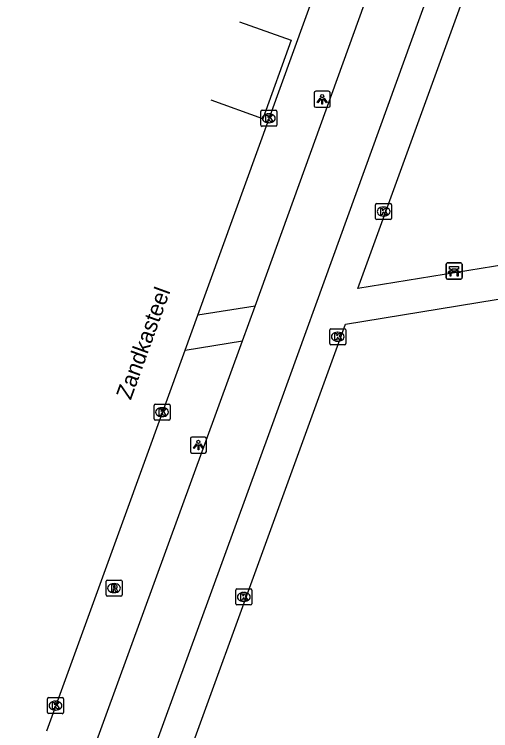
# Model space of a CAD drawing. Extents: x 156664 to 157568, y 383571 to 384421.
# Drawn here: x 156762.62 to 156792.33, y 384130.69 to 384175.37 of the extents above; entities that cross this region are included whole.
import ezdxf

# ---------------------------------------------------------------- set-up
doc = ezdxf.new("R2010")
doc.units = 0
for name, color, linetype in [('IMGEO_Bank', 7, 'Continuous'), ('IMGEO_Fietspad_open', 7, 'Continuous'), ('IMGEO_Kolk', 7, 'Continuous'), ('IMGEO_Lichtpunt', 7, 'Continuous'), ('IMGEO_Openbare_ruimte_label', 7, 'Continuous'), ('IMGEO_Rijbaan_lokaal_open', 7, 'Continuous'), ('IMGEO_Rioolput', 7, 'Continuous'), ('IMGEO_Voetpad_open', 7, 'Continuous')]:
    doc.layers.add(name, color=color, linetype=linetype)

msp = doc.modelspace()

# ---------------------------------------------------------------- linework, layer by layer
at = {"layer": 'IMGEO_Bank'}
for p, q in [((156789.62, 384159.863), (156790.461, 384159.863)), ((156790.461, 384159.863), (156789.62, 384159.863)), ((156789.545, 384158.938), (156789.545, 384159.779)), ((156789.545, 384159.779), (156789.545, 384158.938)), ((156789.854, 384159.369), (156789.854, 384159.475)), ((156789.898, 384159.475), (156789.898, 384159.369)), ((156790.186, 384159.481), (156789.904, 384159.481)), ((156790.192, 384159.369), (156790.192, 384159.475)), ((156790.236, 384159.475), (156790.236, 384159.369)), ((156790.545, 384159.788), (156790.545, 384158.947)), ((156790.545, 384158.947), (156790.545, 384159.788)), ((156790.242, 384159.261), (156789.849, 384159.261)), ((156789.904, 384159.363), (156790.186, 384159.363)), ((156790.47, 384158.863), (156789.629, 384158.863)), ((156789.629, 384158.863), (156790.47, 384158.863))]:
    msp.add_line(p, q, dxfattribs=at)
for points in [[(156789.848, 384159.481), (156789.762, 384159.481), (156789.762, 384159.642), (156790.325, 384159.642), (156790.325, 384159.481), (156790.242, 384159.481)], [(156789.792, 384159.261), (156789.65, 384159.261), (156789.762, 384159.363), (156789.848, 384159.363)], [(156789.842, 384159.254), (156789.842, 384159.047), (156789.799, 384159.047), (156789.799, 384159.254)], [(156790.242, 384159.363), (156790.325, 384159.363), (156790.437, 384159.261), (156790.298, 384159.261)], [(156790.292, 384159.254), (156790.292, 384159.047), (156790.248, 384159.047), (156790.248, 384159.254)]]:
    msp.add_lwpolyline(points, dxfattribs=at)
for centre, radius, start, end in [((156789.623, 384159.785), 0.0779, 92.4484, 184.2845), ((156789.623, 384159.785), 0.0779, 92.4484, 184.2845), ((156790.467, 384159.785), 0.0779, 2.4484, 94.2845), ((156790.467, 384159.785), 0.0779, 2.4484, 94.2845), ((156789.847, 384159.474), 0.00671, 2.8957, 87.1043), ((156789.904, 384159.474), 0.00671, 92.8957, 177.1043), ((156790.186, 384159.474), 0.00671, 2.8957, 87.1043), ((156790.243, 384159.474), 0.00671, 92.8957, 177.1043), ((156789.792, 384159.254), 0.00671, 2.8957, 87.1043), ((156789.849, 384159.254), 0.00671, 92.8957, 177.1043), ((156789.847, 384159.37), 0.00671, 272.8957, 357.1043), ((156789.904, 384159.37), 0.00671, 182.8957, 267.1043), ((156790.186, 384159.37), 0.00671, 272.8957, 357.1043), ((156790.243, 384159.37), 0.00671, 182.8957, 267.1043), ((156790.241, 384159.254), 0.00671, 2.8957, 87.1043), ((156790.298, 384159.254), 0.00671, 92.8957, 177.1043), ((156789.623, 384158.941), 0.0779, 182.4484, 274.2845), ((156789.623, 384158.941), 0.0779, 182.4484, 274.2845), ((156790.467, 384158.941), 0.0779, 272.4484, 4.2845), ((156790.467, 384158.941), 0.0779, 272.4484, 4.2845)]:
    msp.add_arc(centre, radius, start, end, dxfattribs=at)
at = {"layer": 'IMGEO_Fietspad_open'}
for points in [[(156833.031, 384293.583), (156831.476, 384295.664), (156797.885, 384202.753), (156781.915, 384158.669), (156778.633, 384149.604), (156765.945, 384114.759), (156745.635, 384058.756), (156737.507, 384036.302), (156716.373, 383978.18), (156709.217, 383958.49), (156701.659, 383937.694), (156690.408, 383906.735), (156677.045, 383870.138), (156675.34, 383865.46)], [(156777.633, 384157.17), (156795.089, 384205.43)], [(156776.852, 384155.017), (156777.633, 384157.17)], [(156765.926, 384125.001), (156776.852, 384155.017)]]:
    msp.add_lwpolyline(points, dxfattribs=at)
at = {"layer": 'IMGEO_Kolk'}
for p, q in [((156777.994, 384168.46), (156777.994, 384169.312)), ((156778.069, 384169.386), (156778.921, 384169.386)), ((156778.995, 384169.312), (156778.995, 384168.46)), ((156778.482, 384169.166), (156778.507, 384169.166)), ((156778.921, 384168.386), (156778.069, 384168.386)), ((156778.505, 384168.606), (156778.48, 384168.606)), ((156785.148, 384162.645), (156785.148, 384163.497)), ((156785.223, 384163.571), (156786.075, 384163.571)), ((156786.149, 384163.497), (156786.149, 384162.645)), ((156785.636, 384163.351), (156785.661, 384163.351)), ((156786.075, 384162.571), (156785.223, 384162.571)), ((156785.659, 384162.791), (156785.634, 384162.791)), ((156782.292, 384154.837), (156782.292, 384155.689)), ((156782.367, 384155.763), (156783.219, 384155.763)), ((156782.78, 384155.543), (156782.805, 384155.543)), ((156783.293, 384155.689), (156783.293, 384154.837)), ((156782.803, 384154.983), (156782.778, 384154.983)), ((156783.219, 384154.763), (156782.367, 384154.763)), ((156771.336, 384150.132), (156771.336, 384150.984)), ((156771.411, 384151.058), (156772.263, 384151.058)), ((156772.337, 384150.984), (156772.337, 384150.132)), ((156771.824, 384150.838), (156771.849, 384150.838)), ((156772.263, 384150.058), (156771.411, 384150.058)), ((156771.847, 384150.278), (156771.822, 384150.278)), ((156776.432, 384138.608), (156776.432, 384139.46)), ((156776.507, 384139.534), (156777.359, 384139.534)), ((156776.92, 384139.314), (156776.945, 384139.314)), ((156777.433, 384139.46), (156777.433, 384138.608)), ((156777.359, 384138.534), (156776.507, 384138.534)), ((156776.943, 384138.754), (156776.918, 384138.754)), ((156764.689, 384131.828), (156764.689, 384132.68)), ((156764.764, 384132.754), (156765.616, 384132.754)), ((156765.69, 384132.68), (156765.69, 384131.828)), ((156765.177, 384132.534), (156765.202, 384132.534)), ((156765.616, 384131.754), (156764.764, 384131.754)), ((156765.2, 384131.974), (156765.175, 384131.974))]:
    msp.add_line(p, q, dxfattribs=at)
for points in [[(156777.994, 384168.46), (156777.994, 384169.312)], [(156778.069, 384169.386), (156778.921, 384169.386)], [(156778.995, 384169.312), (156778.995, 384168.46)], [(156778.315, 384169.086), (156778.438, 384169.086), (156778.438, 384168.935), (156778.568, 384169.086), (156778.732, 384169.086), (156778.586, 384168.935), (156778.739, 384168.686), (156778.587, 384168.686), (156778.502, 384168.85), (156778.438, 384168.783), (156778.438, 384168.686), (156778.315, 384168.686), (156778.315, 384169.086)], [(156778.921, 384168.386), (156778.069, 384168.386)], [(156785.148, 384162.645), (156785.148, 384163.497)], [(156785.223, 384163.571), (156786.075, 384163.571)], [(156786.149, 384163.497), (156786.149, 384162.645)], [(156785.469, 384163.271), (156785.592, 384163.271), (156785.592, 384163.12), (156785.722, 384163.271), (156785.886, 384163.271), (156785.74, 384163.12), (156785.893, 384162.871), (156785.741, 384162.871), (156785.656, 384163.035), (156785.592, 384162.968), (156785.592, 384162.871), (156785.469, 384162.871), (156785.469, 384163.271)], [(156786.075, 384162.571), (156785.223, 384162.571)], [(156782.292, 384154.837), (156782.292, 384155.689)], [(156782.367, 384155.763), (156783.219, 384155.763)], [(156782.613, 384155.463), (156782.736, 384155.463), (156782.736, 384155.312), (156782.866, 384155.463), (156783.03, 384155.463), (156782.884, 384155.312), (156783.037, 384155.063), (156782.885, 384155.063), (156782.8, 384155.227), (156782.736, 384155.16), (156782.736, 384155.063), (156782.613, 384155.063), (156782.613, 384155.463)], [(156783.293, 384155.689), (156783.293, 384154.837)], [(156783.219, 384154.763), (156782.367, 384154.763)], [(156771.336, 384150.132), (156771.336, 384150.984)], [(156771.411, 384151.058), (156772.263, 384151.058)], [(156772.337, 384150.984), (156772.337, 384150.132)], [(156771.657, 384150.758), (156771.78, 384150.758), (156771.78, 384150.607), (156771.91, 384150.758), (156772.074, 384150.758), (156771.928, 384150.607), (156772.081, 384150.358), (156771.929, 384150.358), (156771.844, 384150.522), (156771.78, 384150.455), (156771.78, 384150.358), (156771.657, 384150.358), (156771.657, 384150.758)], [(156772.263, 384150.058), (156771.411, 384150.058)], [(156776.432, 384138.608), (156776.432, 384139.46)], [(156776.507, 384139.534), (156777.359, 384139.534)], [(156777.433, 384139.46), (156777.433, 384138.608)], [(156776.753, 384139.234), (156776.876, 384139.234), (156776.876, 384139.083), (156777.006, 384139.234), (156777.17, 384139.234), (156777.024, 384139.083), (156777.177, 384138.834), (156777.025, 384138.834), (156776.94, 384138.998), (156776.876, 384138.931), (156776.876, 384138.834), (156776.753, 384138.834), (156776.753, 384139.234)], [(156777.359, 384138.534), (156776.507, 384138.534)], [(156764.689, 384131.828), (156764.689, 384132.68)], [(156764.764, 384132.754), (156765.616, 384132.754)], [(156765.69, 384132.68), (156765.69, 384131.828)], [(156765.01, 384132.454), (156765.133, 384132.454), (156765.133, 384132.303), (156765.263, 384132.454), (156765.427, 384132.454), (156765.281, 384132.303), (156765.434, 384132.054), (156765.282, 384132.054), (156765.197, 384132.218), (156765.133, 384132.151), (156765.133, 384132.054), (156765.01, 384132.054), (156765.01, 384132.454)], [(156765.616, 384131.754), (156764.764, 384131.754)]]:
    msp.add_lwpolyline(points, dxfattribs=at)
for centre, start, end in [((156778.071, 384169.31), 91.552, 178.448), ((156778.071, 384169.31), 91.552, 178.448), ((156778.919, 384169.31), 1.552, 88.448), ((156778.919, 384169.31), 1.552, 88.448), ((156778.071, 384168.462), 181.552, 268.448), ((156778.071, 384168.462), 181.552, 268.448), ((156778.919, 384168.462), 271.552, 358.448), ((156778.919, 384168.462), 271.552, 358.448), ((156785.225, 384163.495), 91.552, 178.448), ((156785.225, 384163.495), 91.552, 178.448), ((156786.073, 384163.495), 1.552, 88.448), ((156786.073, 384163.495), 1.552, 88.448), ((156785.225, 384162.647), 181.552, 268.448), ((156785.225, 384162.647), 181.552, 268.448), ((156786.073, 384162.647), 271.552, 358.448), ((156786.073, 384162.647), 271.552, 358.448), ((156782.369, 384155.687), 91.552, 178.448), ((156782.369, 384155.687), 91.552, 178.448), ((156783.217, 384155.687), 1.552, 88.448), ((156783.217, 384155.687), 1.552, 88.448), ((156782.369, 384154.839), 181.552, 268.448), ((156782.369, 384154.839), 181.552, 268.448), ((156783.217, 384154.839), 271.552, 358.448), ((156783.217, 384154.839), 271.552, 358.448), ((156771.413, 384150.982), 91.552, 178.448), ((156771.413, 384150.982), 91.552, 178.448), ((156772.261, 384150.982), 1.552, 88.448), ((156772.261, 384150.982), 1.552, 88.448), ((156771.413, 384150.134), 181.552, 268.448), ((156771.413, 384150.134), 181.552, 268.448), ((156772.261, 384150.134), 271.552, 358.448), ((156772.261, 384150.134), 271.552, 358.448), ((156776.509, 384139.458), 91.552, 178.448), ((156776.509, 384139.458), 91.552, 178.448), ((156777.357, 384139.458), 1.552, 88.448), ((156777.357, 384139.458), 1.552, 88.448), ((156776.509, 384138.61), 181.552, 268.448), ((156776.509, 384138.61), 181.552, 268.448), ((156777.357, 384138.61), 271.552, 358.448), ((156777.357, 384138.61), 271.552, 358.448), ((156764.766, 384132.678), 91.552, 178.448), ((156764.766, 384132.678), 91.552, 178.448), ((156765.614, 384132.678), 1.552, 88.448), ((156765.614, 384132.678), 1.552, 88.448), ((156764.766, 384131.83), 181.552, 268.448), ((156764.766, 384131.83), 181.552, 268.448), ((156765.614, 384131.83), 271.552, 358.448), ((156765.614, 384131.83), 271.552, 358.448)]:
    msp.add_arc(centre, 0.0765, start, end, dxfattribs=at)
for centre, major_axis, ratio, start_param, end_param in [((156778.481, 384168.886), (-0.387, 0.002), 0.722429, 4.712389, 7.853982), ((156778.506, 384168.886), (-0.39, 0.002), 0.717154, 1.570796, 4.712389), ((156785.635, 384163.071), (-0.387, 0.002), 0.722429, 4.712389, 7.853982), ((156785.66, 384163.071), (-0.39, 0.002), 0.717154, 1.570796, 4.712389), ((156782.779, 384155.263), (-0.387, 0.002), 0.722429, 4.712389, 7.853982), ((156782.804, 384155.263), (-0.39, 0.002), 0.717154, 1.570796, 4.712389), ((156771.823, 384150.558), (-0.387, 0.002), 0.722429, 4.712389, 7.853982), ((156771.848, 384150.558), (-0.39, 0.002), 0.717154, 1.570796, 4.712389), ((156776.919, 384139.034), (-0.387, 0.002), 0.722429, 4.712389, 7.853982), ((156776.944, 384139.034), (-0.39, 0.002), 0.717154, 1.570796, 4.712389), ((156765.176, 384132.254), (-0.387, 0.002), 0.722429, 4.712389, 7.853982), ((156765.201, 384132.254), (-0.39, 0.002), 0.717154, 1.570796, 4.712389)]:
    msp.add_ellipse(centre, major_axis=major_axis, ratio=ratio, start_param=start_param, end_param=end_param, dxfattribs=at)
at = {"layer": 'IMGEO_Lichtpunt'}
for p, q in [((156781.323, 384170.474), (156781.323, 384169.667)), ((156781.323, 384170.474), (156781.323, 384169.667)), ((156782.225, 384170.569), (156781.417, 384170.569)), ((156782.225, 384170.569), (156781.417, 384170.569)), ((156782.319, 384169.667), (156782.319, 384170.474)), ((156782.319, 384169.667), (156782.319, 384170.474)), ((156781.417, 384169.573), (156782.225, 384169.573)), ((156781.417, 384169.573), (156782.225, 384169.573)), ((156773.602, 384148.911), (156773.602, 384148.104)), ((156773.602, 384148.911), (156773.602, 384148.104)), ((156774.504, 384149.006), (156773.696, 384149.006)), ((156774.504, 384149.006), (156773.696, 384149.006)), ((156774.598, 384148.104), (156774.598, 384148.911)), ((156774.598, 384148.104), (156774.598, 384148.911)), ((156773.696, 384148.01), (156774.504, 384148.01)), ((156773.696, 384148.01), (156774.504, 384148.01))]:
    msp.add_line(p, q, dxfattribs=at)
for points in [[(156781.697, 384170.138), (156781.736, 384170.11), (156781.548, 384169.848), (156781.51, 384169.875), (156781.697, 384170.138)], [(156781.909, 384170.11), (156781.947, 384170.137), (156782.134, 384169.875), (156782.095, 384169.847), (156781.909, 384170.11)], [(156781.799, 384170.09), (156781.846, 384170.09), (156781.846, 384169.768), (156781.799, 384169.768), (156781.799, 384170.09)], [(156773.976, 384148.575), (156774.015, 384148.547), (156773.827, 384148.285), (156773.789, 384148.312), (156773.976, 384148.575)], [(156774.078, 384148.527), (156774.125, 384148.527), (156774.125, 384148.205), (156774.078, 384148.205), (156774.078, 384148.527)], [(156774.188, 384148.547), (156774.226, 384148.574), (156774.413, 384148.312), (156774.374, 384148.284), (156774.188, 384148.547)]]:
    msp.add_lwpolyline(points, dxfattribs=at)
for centre in [(156781.822, 384170.272), (156774.101, 384148.709)]:
    msp.add_circle(centre, 0.0994, dxfattribs=at)
for centre, start, end in [((156781.417, 384170.474), 90, 180), ((156781.417, 384170.474), 90, 180), ((156782.225, 384170.474), 0, 90), ((156782.225, 384170.474), 0, 90), ((156781.417, 384169.667), 180, 270), ((156781.417, 384169.667), 180, 270), ((156782.225, 384169.667), 270, 0), ((156782.225, 384169.667), 270, 360), ((156773.696, 384148.911), 90, 180), ((156773.696, 384148.911), 90, 180), ((156774.504, 384148.911), 0, 90), ((156774.504, 384148.911), 0, 90), ((156773.696, 384148.104), 180, 270), ((156773.696, 384148.104), 180, 270), ((156774.504, 384148.104), 270, 0), ((156774.504, 384148.104), 270, 360)]:
    msp.add_arc(centre, 0.0946, start, end, dxfattribs=at)
at = {"layer": 'IMGEO_Rijbaan_lokaal_open'}
for points in [[(156774.062, 384156.603), (156792.708, 384208.042)], [(156776.667, 384174.913), (156779.88, 384173.769), (156778.111, 384168.86), (156774.9, 384170.016)], [(156773.276, 384154.434), (156774.062, 384156.603)], [(156764.651, 384130.687), (156769.391, 384143.716), (156773.276, 384154.434)]]:
    msp.add_lwpolyline(points, dxfattribs=at)
at = {"layer": 'IMGEO_Rioolput'}
for p, q in [((156768.341, 384139.156), (156768.341, 384140.008)), ((156768.416, 384140.082), (156769.268, 384140.082)), ((156768.829, 384139.862), (156768.854, 384139.862)), ((156769.342, 384140.008), (156769.342, 384139.156)), ((156769.268, 384139.082), (156768.416, 384139.082)), ((156768.852, 384139.302), (156768.827, 384139.302))]:
    msp.add_line(p, q, dxfattribs=at)
for points in [[(156768.341, 384139.156), (156768.341, 384140.008)], [(156768.416, 384140.082), (156769.268, 384140.082)], [(156768.93, 384139.78), (156768.678, 384139.782), (156768.678, 384139.382)], [(156769.342, 384140.008), (156769.342, 384139.156)], [(156768.678, 384139.382), (156768.802, 384139.382), (156768.802, 384139.544), (156768.813, 384139.544)], [(156768.856, 384139.701), (156768.802, 384139.701), (156768.802, 384139.62)], [(156768.802, 384139.62), (156768.854, 384139.62)], [(156768.86, 384139.515), (156768.931, 384139.382), (156769.071, 384139.382), (156769.006, 384139.508)], [(156769.268, 384139.082), (156768.416, 384139.082)]]:
    msp.add_lwpolyline(points, dxfattribs=at)
for centre, radius, start, end in [((156768.418, 384140.006), 0.0765, 91.552, 178.448), ((156768.418, 384140.006), 0.0765, 91.552, 178.448), ((156768.929, 384139.67), 0.109, 350.3612, 89.416), ((156769.266, 384140.006), 0.0765, 1.552, 88.448), ((156769.266, 384140.006), 0.0765, 1.552, 88.448), ((156768.812, 384139.491), 0.0533, 26.0293, 88.6989), ((156768.838, 384139.809), 0.19, 274.7715, 282.9687), ((156768.862, 384139.605), 0.0964, 77.0061, 93.1865), ((156768.876, 384139.662), 0.0378, 276.6634, 79.6772), ((156768.927, 384139.67), 0.112, 277.5842, 350.9817), ((156768.911, 384139.455), 0.108, 29.5134, 73.7905), ((156768.418, 384139.158), 0.0765, 181.552, 268.448), ((156768.418, 384139.158), 0.0765, 181.552, 268.448), ((156769.266, 384139.158), 0.0765, 271.552, 358.448), ((156769.266, 384139.158), 0.0765, 271.552, 358.448)]:
    msp.add_arc(centre, radius, start, end, dxfattribs=at)
for centre, major_axis, ratio, start_param, end_param in [((156768.828, 384139.582), (-0.387, 0.002), 0.722429, 4.712389, 7.853982), ((156768.853, 384139.582), (-0.39, 0.002), 0.717154, 1.570796, 4.712389)]:
    msp.add_ellipse(centre, major_axis=major_axis, ratio=ratio, start_param=start_param, end_param=end_param, dxfattribs=at)
at = {"layer": 'IMGEO_Voetpad_open'}
for points in [[(156804.034, 384161.508), (156784.051, 384158.265), (156799.42, 384200.59), (156813.755, 384184.708)], [(156768.247, 384114.722), (156783.275, 384156.048), (156803.211, 384159.313)], [(156777.633, 384157.17), (156774.062, 384156.603)], [(156773.276, 384154.434), (156776.852, 384155.017)]]:
    msp.add_lwpolyline(points, dxfattribs=at)

# ---------------------------------------------------------------- texts
at = {"layer": 'IMGEO_Openbare_ruimte_label'}
msp.add_text('Zandkasteel', height=1, rotation=70.061, dxfattribs=at).set_placement((156769.884, 384151.274))

doc.saveas('drawing.dxf')
